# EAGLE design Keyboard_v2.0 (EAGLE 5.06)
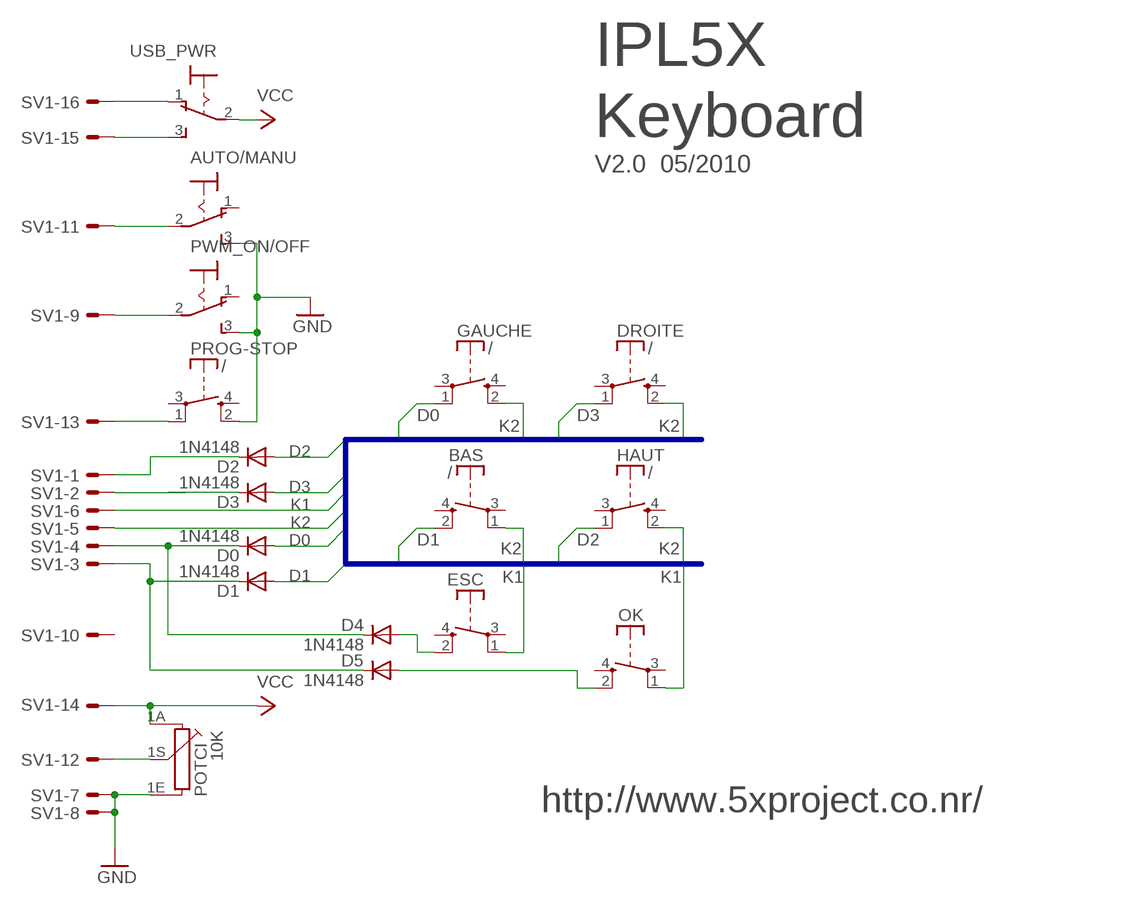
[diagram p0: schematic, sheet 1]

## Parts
10K  POTCI  [POTCI]
AUTO/MANU  320-916  [320-916]
BAS  /  DTE6K  [DTE6K]
D0  1N4148  1N4148DO35-7  [DO35-7]
D1  1N4148  1N4148DO35-7  [DO35-7]
D2  1N4148  1N4148DO35-7  [DO35-7]
D3  1N4148  1N4148DO35-7  [DO35-7]
D4  1N4148  1N4148DO35-7  [DO35-7]
D5  1N4148  1N4148DO35-7  [DO35-7]
DROITE  /  DTE6K  [DTE6K]
ESC  DTE6K  [DTE6K]
GAUCHE  /  DTE6K  [DTE6K]
HAUT  /  DTE6K  [DTE6K]
OK  DTE6K  [DTE6K]
PROG-STOP  /  DTE6K  [DTE6K]
PWM_ON/OFF  320-916  [320-916]
SV1  ML16LE  [ML16L]
USB_PWR  320-916  [320-916]

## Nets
AUTO/MAN: AUTO/MANU.2(P) SV1.11
D0: D0.A GAUCHE.1(P)
D1: BAS.2(S) D1.A
D2: D2.A HAUT.1(P)
D3: D3.A DROITE.1(P)
GND: 10K.1E AUTO/MANU.3(S) PROG-STOP.2(S) PWM_ON/OFF.3(S) SV1.7 SV1.8
K1: ESC.1(P) OK.1(P) SV1.6
K2: BAS.1(P) DROITE.2(S) GAUCHE.2(S) HAUT.2(S) SV1.5
KEY1: D2.C SV1.1
KEY2: D3.C SV1.2
KEY3: D1.C D5.C SV1.3
KEY4: D0.C D4.C SV1.4
N$6: D4.A ESC.2(S)
N$7: D5.A OK.2(S)
N$12: SV1.15 USB_PWR.3(S)
N$13: SV1.16 USB_PWR.1(O)
POT: 10K.1S SV1.12
PROG: PROG-STOP.1(P) SV1.13
PWM0N/OFF: PWM_ON/OFF.2(P) SV1.9
VCC: 10K.1A SV1.14 USB_PWR.2(P)
Unconnected: AUTO/MANU.1(O) BAS.3(P) BAS.4(S) DROITE.3(P) DROITE.4(S) ESC.3(P) ESC.4(S) GAUCHE.3(P) GAUCHE.4(S) HAUT.3(P) HAUT.4(S) OK.3(P) OK.4(S) PROG-STOP.3(P) PROG-STOP.4(S) PWM_ON/OFF.1(O) SV1.10

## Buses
D0,D1,D2,D3,E,RS,K1,K2

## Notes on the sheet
- IPL5X
- Keyboard
- V2.0  05/2010
- http://www.5xproject.co.nr/

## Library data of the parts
10K = potentiometres:POTCI
AUTO/MANU PWM_ON/OFF USB_PWR = switch:320-916: TOGGLE SWITCH distributor RS Components
BAS DROITE ESC GAUCHE HAUT OK PROG-STOP = switch-ipl5x:DT: ITT SWITCH
D0 D1-D5 = diode:1N4148: DIODE
SV1 = con-harting-ml:ML16?E: HARTING

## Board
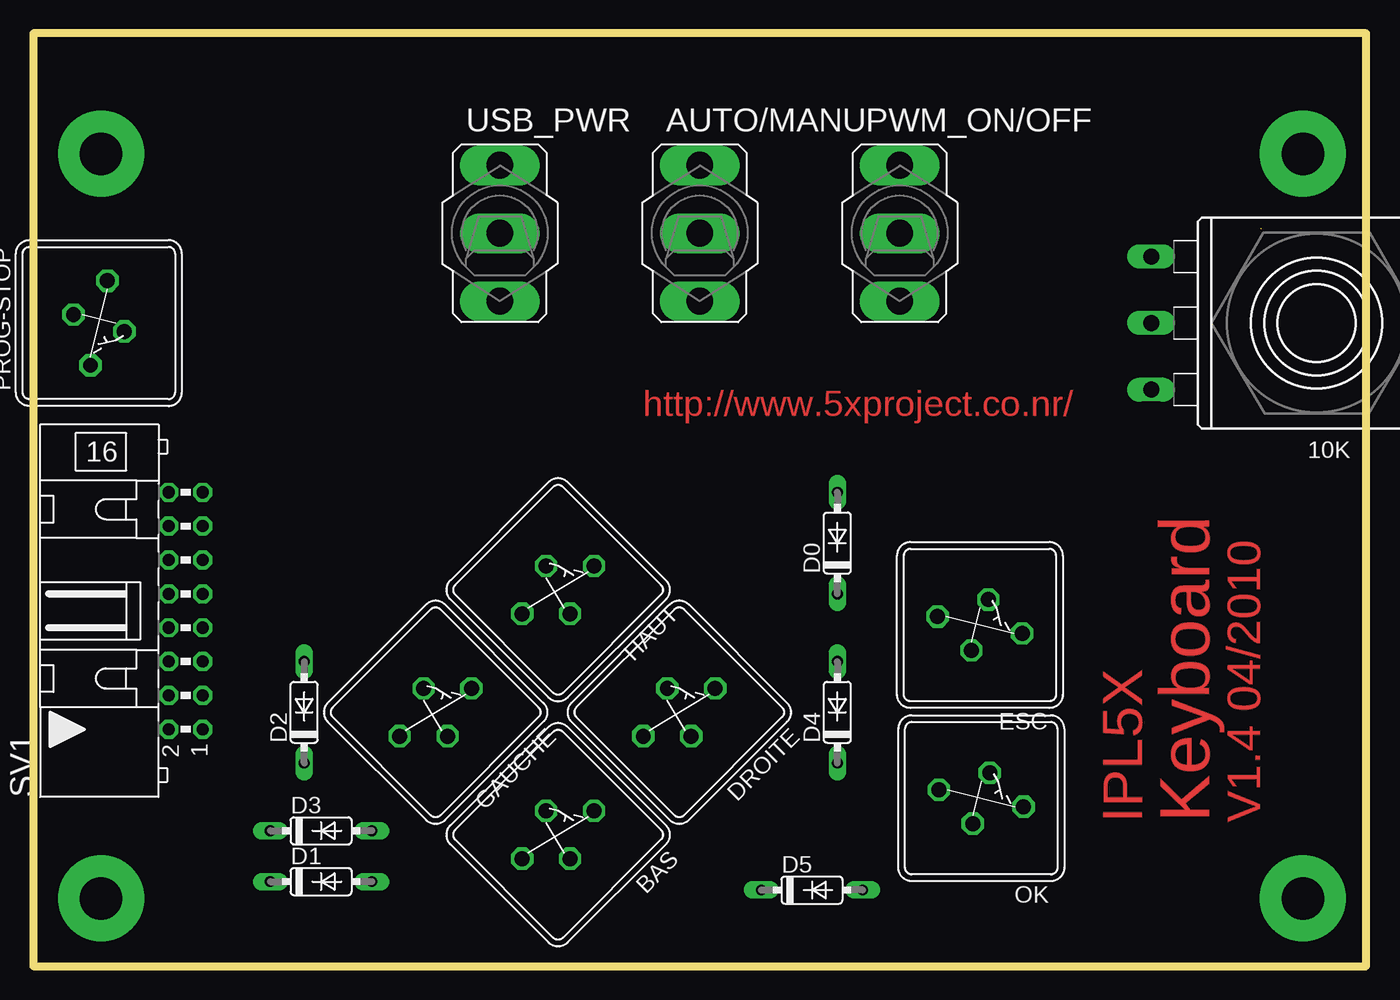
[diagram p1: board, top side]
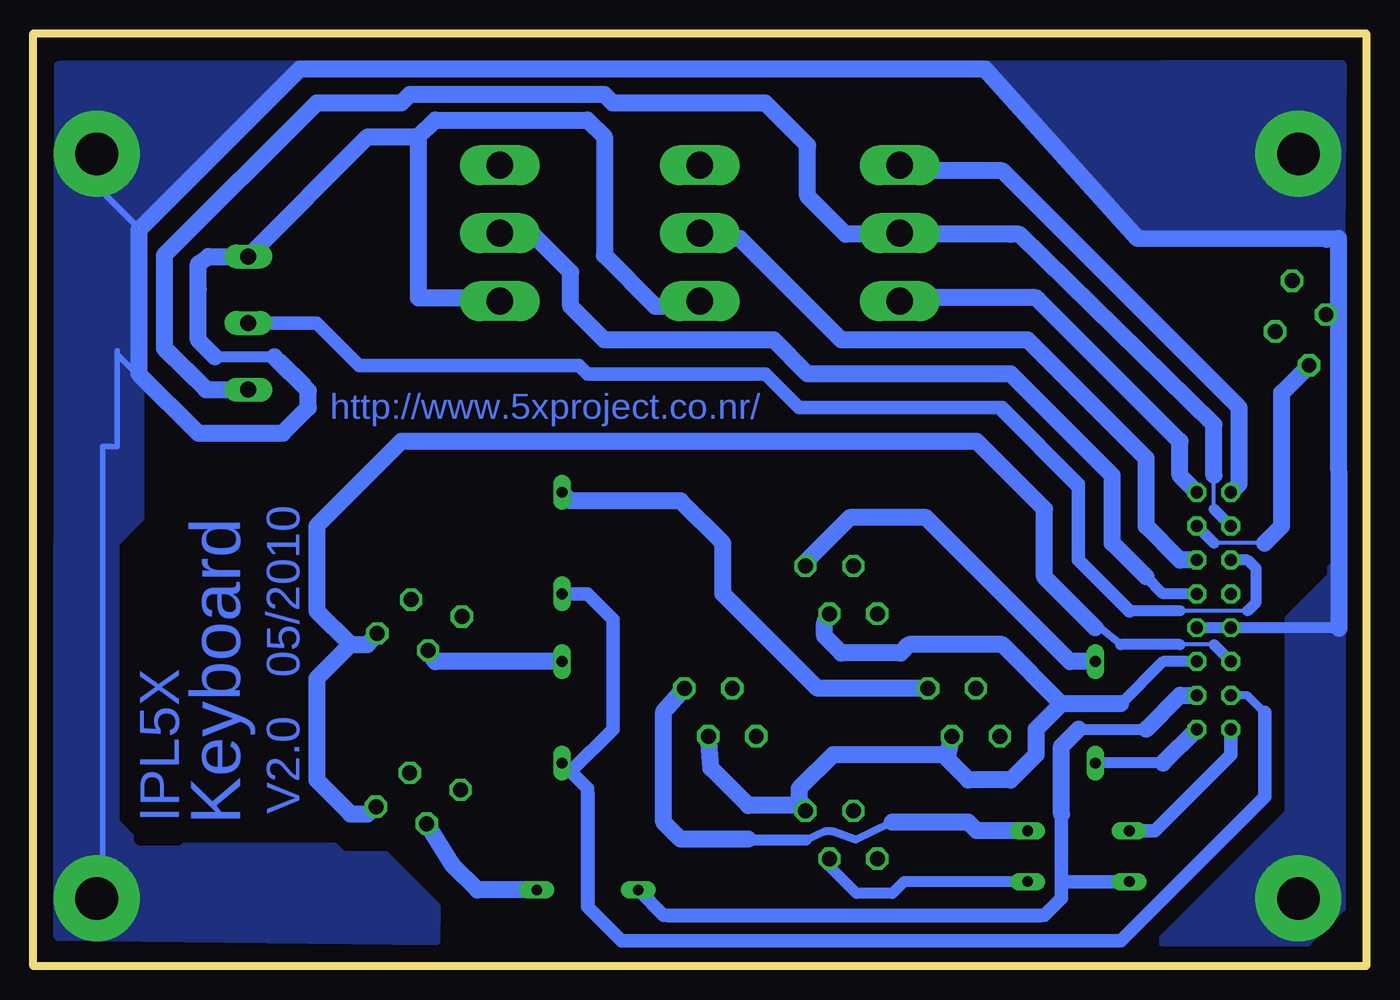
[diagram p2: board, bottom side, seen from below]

Size 100 x 70 mm. Coordinates in mm from the lower left corner, seen from the top.
Outline: 0,0 100,0 100,70 0,70 0,0
Copper layers (1*16): Top 0.035mm / dielectric 1.5mm / Bottom 0.035mm
Design rules "default *": minimum track width 10mil, minimum drill 24mil, track to track 15mil, track to pad 15mil, pad to pad 15mil, via to via 15mil, smd to smd 8mil, copper to edge 40mil, drill to drill 8mil, minimum pad ring 10mil, minimum via ring 8mil, stop-mask expansion 4mil, vias tented up to drill 0mil, thermal gap 10mil
tRestrict: area 4,74.4 to 96,97.4
vRestrict: area -11,65 to 111,107

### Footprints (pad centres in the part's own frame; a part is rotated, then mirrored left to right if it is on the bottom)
POTCI = drill 1.2 long: 1A -5,12.4; 1E 5,12.4; 1S 0,12.4; S1 -5,12.4; S2 5,12.4
320-916 = drill 2.007 long: 1 0,5.098; 2 0,0; 3 0,-5.098
DTE6K = drill 1.118 octagon: 1 -3.175,0.635; 2 0.635,1.905; 3 3.175,-0.635; 4 -0.635,-1.905
DO35-7 = drill 0.813 long: A 3.81,0; C -3.81,0
ML16L = drill 0.914 octagon: 1 -8.89,-1.27; 2 -8.89,1.27; 3 -6.35,-1.27; 4 -6.35,1.27; 5 -3.81,-1.27; 6 -3.81,1.27; 7 -1.27,-1.27; 8 -1.27,1.27; 9 1.27,-1.27; 10 1.27,1.27; 11 3.81,-1.27; 12 3.81,1.27; 13 6.35,-1.27; 14 6.35,1.27; 15 8.89,-1.27; 16 8.89,1.27

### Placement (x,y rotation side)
10K  96.28,48.26 90 top
AUTO/MANU  50,55 0 top
BAS  39.37,9.86 225 top
D0  60.33,31.75 90 top
D1  21.59,6.35 0 top
D2  20.32,19.05 90 top
D3  21.59,10.16 0 top
D4  60.33,19.05 90 top
D5  58.42,5.71 0 top
DROITE  48.46,19.05 225 top
ESC  71.02,25.6 180 top
GAUCHE  30.18,19.05 225 top
HAUT  39.37,28.24 225 top
OK  71.12,12.6 180 top
PROG-STOP  4.92,48.26 90 top
PWM_ON/OFF  65,55 0 top
SV1  11.43,26.67 90 top
USB_PWR  35,55 0 top

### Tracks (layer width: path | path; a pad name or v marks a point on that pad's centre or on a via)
AUTO/MAN
  Bottom 0.406: SV1.11 12.7,30.57 | 47.62,54.61 49.53,55.24 49.77,55 AUTO/MANU.2
  Bottom 1.27: SV1.11 13.97,30.48 16.51,33.02 16.51,38.1 25.4,46.99 39.37,46.99 46.99,54.61 47.62,54.61 50.16,54.93
D0
  Bottom 1.27: D0.A 59.69,34.92 51.44,34.92 48.26,31.75 48.26,27.94 41.17,20.85 GAUCHE.1
D1
  Bottom 0.6: 40.26,7.49 BAS.2
  Bottom 0.813: D1.A 34.67,6.35 35.56,5.46 38.23,5.46 40.26,7.49
D2
  Bottom 1.27: D2.A 22.23,22.86 33.02,33.66 38.73,33.66 42.06,30.33 HAUT.1
D3
  Bottom 0.406: 46.72,9.62 46.35,9.53
  Bottom 0.61: 42.02,9.46 40.62,10.11 40.04,10.11 38.3,9.5 35.66,10.76
  Bottom 0.813: 35.56,10.79 35.66,10.76 | 42.02,9.46 46.48,9.46 46.72,9.62
  Bottom 1.27: DROITE.1 52.7,19.09 52.7,10.79 51.44,9.53 46.35,9.53 | D3.A 29.21,10.16 29.84,10.79 35.56,10.79
GND  (via drill 3.2 pad 6.45)  (1 unrouted)
  Bottom 0.406: 66.67,50.12 PWM_ON/OFF.3 71.12,50.35 | AUTO/MANU.3 50.19,49.53 53.34,49.53 | 81.92,45.72 81.28,45.72 79.38,43.81 79.38,43.18 | v95.25,5.08 94.8,5.08 94.8,39 93.7,39 93.7,45.9 | 93.7,45.9 93.7,46.2 | 93.7,45.9 87.8,40 87.4,40 | 87.63,40.01 87.59,40.01 87.5,40.1 | v95.25,60.96 95.25,58.55 92.1,55.4 | 92.08,55.24 92.08,55.23 92.1,55.2 92.1,55.3 | 87.63,50.8 87.41,50.16 | 2.02,25.41 2.13,25.3 2.4,25.3 2.5,25.4 | PROG-STOP.2 2.17,48.9 2.06,49 | 83.91,53.25 10K.1E
  Bottom 0.813: SV1.7 SV1.8 2.5,25.4 | 81.92,45.72 86.36,45.72
  Bottom 1.27: 81.92,45.72 79.38,43.18 79.38,41.91 81.28,40.01 87.63,40.01 92.08,44.45 92.08,55.24 80.01,67.31 28.57,67.31 17.14,54.61 2.98,54.55 2.07,54.61 2.06,49 2.02,25.36 | 86.36,45.72 87.63,46.99 87.63,50.8 87.63,52.7 86.85,53.25 83.91,53.25 | 64.77,50.16 71.12,50.16 71.12,50.35 71.12,62.23 | 71.12,62.23 69.85,63.5 58.42,63.5 57.15,62.23 57.15,53.34 53.34,49.53 49.53,49.53 | PROG-STOP.2 2.13,48.9 | 71.12,62.23 74.91,62.23 10K.1E
  other vias: 5.08,5.08 5.08,60.96
  pour Bottom: 79.81,67.55 98.06,67.51 98.06,56.38 90.81,56.52
  pour Bottom: 28.85,67.58 1.88,67.64 1.97,54.57 16.51,54.61 17.14,55.24 17.14,55.88
  pour Bottom: 92.11,56.38 92.08,33.66 93.98,31.75 93.98,10.79 92.08,8.89 77.47,8.89 76.83,8.26 73.66,8.26 69.85,4.45 69.88,1.93 98.09,2.27 98.06,61.28
  pour Bottom: 12.7,1.91 4.45,1.91 1.91,4.45 1.91,29.21 2.54,29.84 2.54,29.21 5.71,26.04 5.71,11.43 15.24,1.91
K1
  Bottom 0.305: 11.43,24.13 13.97,24.13
  Bottom 0.406: 19.94,25.4 20.32,25.4
  Bottom 0.61: 18.41,24.13 19.94,25.4
  Bottom 0.813: SV1.6 11.43,24.13 | 13.97,24.13 18.41,24.13
  Bottom 1.27: 20.32,25.4 24.13,29.21 24.13,34.29 29.21,39.37 62.23,39.37 | 62.23,39.37 63.5,39.37 | 76.2,24.13 78.74,21.59 78.74,13.97 76.2,11.43 74.93,11.43 OK.1 | ESC.1 74.93,24.13 76.2,24.13 | 76.2,24.13 78.74,26.67 78.74,33.02 72.39,39.37 62.23,39.37
K2
  Bottom 0.813: 18.41,19.68 15.24,22.86 SV1.5 12.38,22.86
  Bottom 1.27: 18.41,19.68 22.86,19.68 | 22.86,19.68 24.77,17.78 24.77,15.88 26.67,13.97 29.84,13.97 31.38,15.5 31.38,15.88 | 31.38,15.88 GAUCHE.2 | DROITE.2 49.16,14.87 46.35,12.06 42.17,12.06 BAS.1 42.55,12.44 42.55,13.34 40.01,15.88 31.38,15.88 | HAUT.2 40.64,25.77 40.64,24.77 39.37,23.5 34.92,23.5 34.29,24.13 27.3,24.13 22.86,19.68
KEY1
  Bottom 0.813: 15.24,15.24 D2.C
  Bottom 1.27: SV1.1 15.24,15.24
KEY2
  Bottom 0.406: SV1.2 10.16,16.04 16,10.2 17.74,10.2 D3.C
  Bottom 1.016: SV1.2 10.16,15.88 15.88,10.16 D3.C
KEY3
  Bottom 0.406: 22.86,11.43 22.9,11.43 22.9,6.6 | 22.9,6.6 22.9,4.7 23.2,4.7 24.4,3.5 52.4,3.5 52.7,3.81 | D1.C 22.65,6.35 22.9,6.6
  Bottom 0.813: 21.59,17.78 16.51,17.78
  Bottom 1.016: 22.86,6.35 22.86,11.43 | 22.86,6.35 22.86,5.08 24.13,3.81 52.7,3.81 D5.C | D1.C 22.86,6.35
  Bottom 1.27: SV1.3 13.97,20.32 16.51,17.78 | 21.59,17.78 22.86,16.51 22.86,11.43
KEY4
  Bottom 0.406: 7.6,19 7.6,12.7 18.1,2.2 56,2.2 58.1,4.3 58.1,13.02 59.69,14.61 D4.C 59.98,14.9 59.2,14.9 56.5,17.6 56.6,17.7 56.6,26.2 58.34,27.94 58.42,27.94
  Bottom 0.61: SV1.4 8.92,20.32 7.6,19
  Bottom 1.016: D0.C 58.42,27.94 56.52,26.04 56.52,17.78 59.69,14.61 | 7.62,19.05 7.62,12.7 18.41,1.91 55.88,1.91 58.42,4.45 58.42,13.34 D4.C
N$6
  Bottom 1.27: D4.A 69.85,22.86 ESC.2
N$7
  Bottom 1.27: OK.2 68.58,7.62 66.67,5.71 D5.A
N$12
  Bottom 0.406: 24.77,50.16 24.32,50.35 USB_PWR.3
  Bottom 1.27: SV1.15 13.97,36.83 13.97,39.37 24.77,50.16 34.92,50.16
N$13
  Bottom 0.406: SV1.16 9.53,36.32 9.53,41.91 27.26,59.65 USB_PWR.1
  Bottom 1.27: SV1.16 9.53,36.2 9.53,41.91 27.3,59.69 35.56,59.69
POT
  Bottom 0.305: 8.89,26.67 13.97,26.67
  Bottom 0.406: 83.82,48.26 10K.1S | 42.55,41.91 27.94,41.91 21.59,35.56
  Bottom 0.813: SV1.12 8.89,30.48 8.26,29.84 8.26,27.3 8.89,26.67 | 13.97,26.67 17.78,26.67
  Bottom 1.016: 17.78,26.67 21.59,30.48 21.59,35.56 21.59,36.2 27.3,41.91 42.55,41.91 45.09,44.45 58.42,44.45 59.05,45.09 75.56,45.09 78.74,48.26 83.82,48.26
PROG
  Bottom 0.305: 7.62,31.75 11.43,31.75
  Bottom 0.813: 11.43,31.75 SV1.13
  Bottom 1.27: PROG-STOP.1 6.35,43.02 6.35,33.02 7.62,31.75
PWM0N/OFF
  Bottom 0.406: 63.5,54.93 64.21,55 PWM_ON/OFF.2
  Bottom 0.813: SV1.9 15.24,27.94 16.51,29.21
  Bottom 1.27: 64.77,54.93 63.5,54.93 62.55,54.93 59.69,52.07 59.69,49.53 57.15,46.99 44.45,46.99 41.91,44.45 26.67,44.45 19.05,36.83 19.05,31.75 16.51,29.21
VCC
  Bottom 0.305: 11.43,34.29 11.43,36.83
  Bottom 0.406: 26.67,54.93 33.02,54.61 33.41,55 USB_PWR.2 39.12,55 41.91,57.78 | 10K.1A 83.95,43.18 86.36,43.18 90.17,46.99
  Bottom 0.813: SV1.14 11.43,34.29
  Bottom 1.27: 11.43,36.83 11.43,40.64 26.04,54.93 26.67,54.93 39.05,54.93 41.91,57.78 41.91,61.59 45.09,64.77 56.52,64.77 57.15,65.41 71.75,65.41 72.39,64.77 78.74,64.77 90.17,53.34 90.17,46.99 90.17,46.35 87.04,43.27 83.82,43.27

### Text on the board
Top: http://www.5xproject.co.nr/ | IPL5X | Keyboard | V1.4 04/2010
Bottom: http://www.5xproject.co.nr/ | Keyboard | IPL5X | V2.0 05/2010
tNames: Position afficheur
